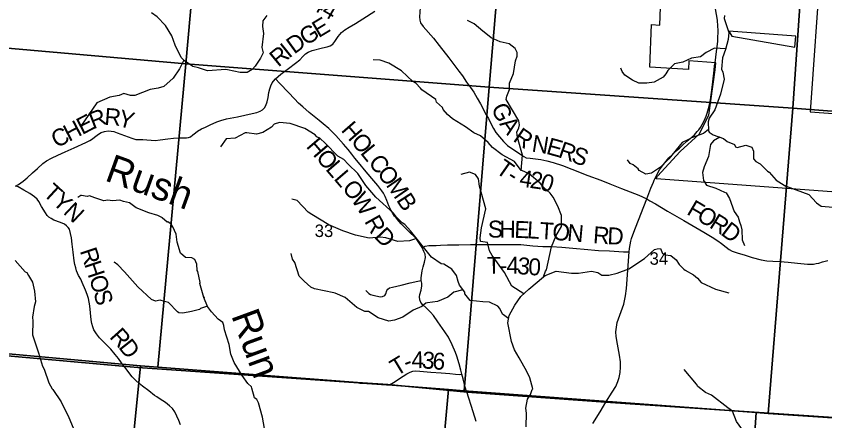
# Model space of a CAD drawing. Extents: x 1878108 to 2183446, y 146837 to 508383.
# Drawn here: x 1990420 to 2004746, y 311060 to 318226 of the extents above; entities that cross this region are included whole.
import ezdxf

# ---------------------------------------------------------------- set-up
doc = ezdxf.new("R2010")
doc.units = 0
for name, color, linetype in [('GM_X_Corporation', 7, 'Continuous'), ('GM_X_County_Road', 7, 'Continuous'), ('GM_X_County_Road_Text', 7, 'Continuous'), ('GM_X_Minor_River', 7, 'Continuous'), ('GM_X_Minor_River_Text', 7, 'Continuous'), ('GM_X_Section', 7, 'Continuous'), ('GM_X_Section_Text', 7, 'Continuous'), ('GM_X_State_Route', 7, 'Continuous'), ('GM_X_Township', 7, 'Continuous'), ('GM_X_Township_Road', 7, 'Continuous'), ('GM_X_Township_Road_Text', 7, 'Continuous')]:
    doc.layers.add(name, color=color, linetype=linetype)

msp = doc.modelspace()

# ---------------------------------------------------------------- linework, layer by layer
at = {"layer": 'GM_X_Corporation'}
for points in [[(2004966, 319101), (2004667, 319124), (2004486, 316532), (2005454, 316459)], [(2005346, 315077), (2001759, 315347), (2001779, 315392), (2002183, 315827), (2002522, 316138), (2002692, 316472), (2002803, 317276), (2002817, 317402), (2002339, 317438), (2002332, 317279), (2001643, 317326), (2001677, 318080), (2001825, 318068), (2001846, 318707)]]:
    msp.add_lwpolyline(points, dxfattribs=at)
msp.add_lwpolyline([(2003046, 317961), (2003096, 317874), (2004216, 317675), (2004230, 317875)], close=True, dxfattribs=at)
at = {"layer": 'GM_X_County_Road'}
for points in [[(1990411, 315215), (1990463, 315243), (1990546, 315306), (1990617, 315365), (1990711, 315450), (1990799, 315530), (1990895, 315617), (1990957, 315663), (1991044, 315711), (1991156, 315762), (1991289, 315821), (1991450, 315892), (1991653, 315988), (1991725, 316022), (1991772, 316051), (1991808, 316082), (1991877, 316137), (1991929, 316164), (1991988, 316183), (1992051, 316193), (1992102, 316192), (1992151, 316182), (1992212, 316161), (1992340, 316113), (1992470, 316067), (1992542, 316045), (1992591, 316042), (1992665, 316043), (1992733, 316038), (1992809, 316028), (1992880, 316027), (1992973, 316039), (1993110, 316056), (1993205, 316068), (1993315, 316070), (1993436, 316071), (1993471, 316076), (1993506, 316091), (1993550, 316123), (1993597, 316161), (1993633, 316191), (1993701, 316229), (1993777, 316261), (1993859, 316301), (1993974, 316353), (1994047, 316381), (1994146, 316406), (1994341, 316445), (1994473, 316471), (1994603, 316501), (1994686, 316520), (1994740, 316542), (1994784, 316567), (1994817, 316600), (1994844, 316643), (1994868, 316708), (1994882, 316784), (1994898, 316876), (1994912, 316939), (1994930, 316991), (1994956, 317045), (1994979, 317078), (1995013, 317115), (1995109, 317198), (1995244, 317299), (1995371, 317393), (1995444, 317452), (1995501, 317512), (1995546, 317558), (1995591, 317589), (1995662, 317616), (1995845, 317666), (1995929, 317681), (1995985, 317702), (1996028, 317733), (1996065, 317779), (1996126, 317869), (1996184, 317937), (1996240, 317982), (1996321, 318032), (1996429, 318099), (1996560, 318179), (1996776, 318316)], [(1992284, 312089), (1992233, 312161), (1992175, 312232), (1992095, 312330), (1992029, 312399), (1991949, 312478), (1991898, 312532), (1991843, 312603), (1991798, 312669), (1991776, 312724), (1991761, 312781), (1991750, 312847), (1991738, 312970), (1991725, 313099), (1991715, 313164), (1991702, 313224), (1991680, 313295), (1991650, 313374), (1991592, 313510), (1991563, 313567), (1991527, 313636), (1991491, 313716), (1991476, 313767), (1991461, 313831), (1991450, 313894), (1991431, 314045), (1991414, 314189), (1991399, 314301), (1991384, 314380), (1991364, 314452), (1991341, 314486), (1991313, 314515), (1991277, 314543), (1991207, 314573), (1991090, 314615), (1991038, 314640), (1990998, 314669), (1990968, 314699), (1990939, 314741), (1990870, 314853), (1990824, 314942), (1990790, 314984), (1990746, 315029), (1990665, 315088), (1990555, 315147), (1990454, 315203), (1990411, 315215)], [(1993331, 310991), (1993301, 311066), (1993269, 311142), (1993229, 311221), (1993187, 311279), (1993139, 311326), (1993063, 311383), (1992972, 311444), (1992913, 311482), (1992872, 311511), (1992770, 311592), (1992660, 311675), (1992600, 311723), (1992548, 311766), (1992477, 311837), (1992398, 311940), (1992332, 312025), (1992300, 312067), (1992284, 312089)]]:
    msp.add_lwpolyline(points, dxfattribs=at)
at = {"layer": 'GM_X_Minor_River'}
for points in [[(1994863, 318240), (1994788, 318144), (1994787, 318042), (1994801, 317920), (1994770, 317669), (1994794, 317579), (1994749, 317481), (1994653, 317341), (1994603, 317284), (1994515, 317228), (1994388, 317230), (1994163, 317278), (1994137, 317280), (1993812, 317259), (1993651, 317309), (1993550, 317336), (1993402, 317436), (1993346, 317492), (1993238, 317713), (1993179, 317878), (1993065, 318062), (1992917, 318215), (1992815, 318285)], [(2002968, 318236), (2002961, 318184), (2003043, 317940), (2003036, 317811), (2002988, 317636), (2002931, 317489), (2002918, 317288), (2002942, 317236), (2002960, 317113), (2002897, 316845), (2002796, 316569), (2002696, 316419), (2002681, 316357), (2002683, 316200), (2002699, 316171), (2002768, 316124), (2002952, 316059), (2003013, 316009), (2003148, 315955), (2003163, 315910), (2003194, 315898), (2003348, 315940), (2003452, 315906), (2003481, 315834), (2003480, 315701), (2003523, 315654), (2003602, 315611), (2003627, 315587), (2003728, 315481), (2003761, 315465), (2003886, 315322), (2004075, 315204)], [(1999368, 315495), (1999391, 315767), (1999301, 316077), (1999292, 316174), (1999323, 316246), (1999339, 316303), (1999328, 316371), (1999102, 316752), (1999115, 316811), (1999159, 316929), (1999160, 317038), (1999232, 317210), (1999264, 317437), (1999296, 317519), (1999294, 317584), (1999261, 317656), (1999154, 317736), (1998993, 317769), (1998834, 317844), (1998714, 317943), (1998685, 317963), (1998531, 318090), (1998415, 318148)], [(2002990, 317645), (2002793, 317661), (2002645, 317585), (2002541, 317509), (2002385, 317484), (2002229, 317410), (2002080, 317380), (2001966, 317267), (2001928, 317205), (2001881, 317144), (2001721, 317060), (2001591, 317037), (2001453, 317042), (2001341, 317090), (2001205, 317182), (2001155, 317246), (2001135, 317305)], [(1993390, 317448), (1993316, 317293), (1993204, 317126), (1993034, 316981), (1992935, 316953), (1992797, 316928), (1992525, 316824), (1992444, 316824), (1992389, 316841), (1992328, 316854), (1992243, 316821), (1992079, 316794), (1991847, 316691), (1991565, 316276)], [(1999379, 315491), (1999368, 315495), (1999248, 315650), (1999030, 315773), (1998856, 315902), (1998781, 315990), (1998648, 316105), (1998530, 316158), (1998380, 316266), (1998149, 316409), (1998062, 316485), (1997984, 316575), (1997972, 316610), (1997866, 316704), (1997853, 316749), (1997606, 316924), (1997585, 316952), (1997503, 317042), (1997449, 317072), (1997249, 317260), (1997023, 317392), (1996866, 317447), (1996746, 317453)], [(1999141, 312874), (1999037, 312951), (1998988, 313047), (1998954, 313088), (1998803, 313160), (1998687, 313170), (1998461, 313192), (1998369, 313307), (1998367, 313339), (1998277, 313464), (1998253, 313530), (1998220, 313634), (1998141, 313744), (1997997, 313835), (1997949, 313840), (1997779, 313960), (1997757, 313990), (1997405, 314426), (1997306, 314537), (1997260, 314569), (1997156, 314664), (1997104, 314736), (1996789, 315023), (1996616, 315228), (1996471, 315437), (1996300, 315608), (1996225, 315687), (1996121, 315746), (1995892, 315979), (1995803, 316060), (1995749, 316088), (1995717, 316122), (1995536, 316237), (1995275, 316323), (1995087, 316344), (1994993, 316314), (1994945, 316263), (1994790, 316167), (1994677, 316139), (1994506, 316158), (1994480, 316158), (1994299, 316066), (1994139, 316052), (1994043, 315910)], [(2002684, 316217), (2002595, 316146), (2002383, 316074), (2002322, 316038), (2002218, 315987), (2001985, 315699), (2001835, 315554), (2001673, 315448), (2001575, 315431), (2001457, 315493), (2001439, 315525), (2001349, 315593), (2001299, 315619), (2001249, 315681)], [(2002887, 316082), (2002771, 316019), (2002722, 315954), (2002685, 315739), (2002609, 315558), (2002580, 315459), (2002598, 315313), (2002651, 315233), (2002818, 315179), (2002971, 315107), (2002999, 315097), (2003057, 315000), (2003139, 314765), (2003209, 314668), (2003237, 314586), (2003257, 314520), (2003277, 314442), (2003283, 314263), (2003321, 314164)], [(1999411, 313307), (1999200, 313445), (1999072, 313689), (1998851, 313990), (1998807, 314069), (1998768, 314215), (1998645, 314237), (1998640, 314302), (1998662, 314477), (1998743, 314814), (1998626, 315216), (1998611, 315345), (1998558, 315422), (1998450, 315461), (1998295, 315425)], [(1999453, 310956), (1999462, 311198), (1999448, 311286), (1999479, 311446), (1999533, 311524), (1999563, 311612), (1999571, 311624), (1999522, 311820), (1999466, 311936), (1999333, 312178), (1999247, 312316), (1999194, 312466), (1999129, 312795), (1999153, 312923), (1999255, 313108), (1999360, 313260), (1999500, 313390), (1999760, 313610), (1999799, 313713), (1999815, 313733), (1999904, 314141), (1999986, 314343), (2000079, 314503), (2000083, 314699), (2000014, 314863), (1999934, 315021), (1999880, 315093), (1999769, 315191), (1999703, 315271), (1999510, 315433), (1999379, 315491)], [(2004062, 315213), (2004460, 315070), (2004598, 314918), (2004680, 314863), (2004896, 314842), (2005164, 314768), (2005755, 314557), (2005985, 314465), (2006145, 314441), (2006267, 314516), (2006291, 314546), (2006337, 314608), (2006397, 314757), (2006397, 314781)], [(1994821, 310923), (1994785, 311123), (1994712, 311377), (1994686, 311437), (1994642, 311469), (1994597, 311641), (1994591, 311661), (1994525, 311719), (1994422, 311863), (1994280, 312091), (1994225, 312241), (1994195, 312411), (1994112, 312670), (1994102, 312746), (1994081, 312800), (1994001, 312860), (1993883, 312988), (1993812, 313084), (1993746, 313242), (1993758, 313248), (1993746, 313244), (1993677, 313492), (1993679, 313508), (1993639, 313706), (1993625, 313720), (1993618, 313834), (1993586, 313918), (1993534, 313946), (1993418, 313955), (1993331, 314031), (1993275, 314221), (1993254, 314363), (1993194, 314497), (1993166, 314541), (1993108, 314583), (1993094, 314577), (1993009, 314655), (1992999, 314659), (1992931, 314697), (1992771, 314746), (1992547, 314832), (1992426, 314920), (1992324, 314942), (1992256, 314967), (1992128, 314955), (1992046, 314967), (1991976, 314957), (1991812, 315009), (1991717, 315042), (1991681, 315032), (1991575, 315048), (1991563, 315050), (1991515, 315012)], [(1997515, 314289), (1997391, 314250), (1997181, 314238), (1996968, 314299), (1996866, 314310), (1996676, 314293), (1996429, 314348), (1996208, 314427), (1995959, 314529), (1995657, 314716), (1995591, 314757), (1995398, 314959), (1995302, 314988)], [(1998336, 313378), (1998174, 313338), (1998065, 313247), (1997885, 313171), (1997709, 313150), (1997679, 313144), (1997606, 313087), (1997453, 313019), (1997268, 312895), (1997120, 312845), (1997022, 312825), (1996833, 312882), (1996662, 312996), (1996600, 312995), (1996454, 313067), (1996247, 313242), (1996071, 313318), (1996046, 313324), (1995707, 313395), (1995641, 313428), (1995520, 313535), (1995433, 313623), (1995355, 313862), (1995313, 313925), (1995294, 314025)], [(1999762, 313611), (1999793, 313634), (1999989, 313713), (2000258, 313675), (2000384, 313674), (2000610, 313713), (2000723, 313687), (2000794, 313642), (2000919, 313640), (2001068, 313676), (2001276, 313752), (2001551, 313934), (2001729, 314095), (2001774, 314108), (2001837, 314114), (2001873, 314025), (2001918, 314002), (2002017, 313987), (2002112, 313908), (2002165, 313828), (2002246, 313748), (2002272, 313728), (2002420, 313646), (2002492, 313587), (2002553, 313510), (2002812, 313390), (2003044, 313326)], [(1990404, 313900), (1990582, 313696), (1990608, 313684), (1990636, 313634), (1990659, 313602), (1990707, 313518), (1990745, 313354), (1990762, 313170), (1990742, 313082), (1990709, 312894), (1990715, 312822), (1990711, 312582), (1990816, 312264), (1990885, 312028), (1990917, 311972), (1991002, 311731), (1991060, 311625), (1991070, 311615), (1991219, 311397), (1991356, 311119), (1991457, 310865)], [(1993811, 313088), (1993688, 313050), (1993670, 313032), (1993526, 312997), (1993374, 312965), (1993300, 312971), (1993278, 312989), (1993118, 313155), (1993048, 313175), (1992971, 313196), (1992891, 313178), (1992817, 313206), (1992578, 313430), (1992340, 313699), (1992223, 313823), (1992159, 313869), (1992159, 313865)], [(2004127, 309586), (2004037, 309660), (2003936, 310065), (2003848, 310216), (2003709, 310380), (2003648, 310545), (2003573, 310663), (2003403, 310809), (2003307, 310874), (2003180, 311048), (2003110, 311232), (2003026, 311290), (2002736, 311515), (2002632, 311560), (2002497, 311668), (2002470, 311706), (2002253, 311968)]]:
    msp.add_lwpolyline(points, dxfattribs=at)
at = {"layer": 'GM_X_Section'}
for points in [[(1988594, 323225), (1993909, 322781), (1993424, 317385), (1988119, 317849)], [(1993909, 322781), (1999255, 322337), (1998801, 316967), (1993424, 317385)], [(1999255, 322337), (2004547, 321948), (2004181, 316598), (1998801, 316967)], [(2004547, 321948), (2009823, 321447), (2009499, 316192), (2004181, 316598)], [(1993424, 317385), (1992928, 312010), (1992620, 312034), (1987478, 312502), (1988119, 317849)], [(1998801, 316967), (1998355, 311588), (1998077, 311612), (1992928, 312010), (1993424, 317385)], [(1998801, 316967), (2004181, 316598), (2003743, 311188), (2003529, 311206), (1998355, 311588)], [(2004181, 316598), (2009499, 316192), (2009160, 310834), (2009010, 310838), (2003743, 311188)], [(1987478, 312502), (1992620, 312034), (1992094, 306704), (1986650, 307162), (1987122, 312538)], [(1992928, 312010), (1998077, 311612), (1997595, 306264), (1992094, 306704), (1992620, 312034)], [(1998077, 311612), (1998355, 311588), (2003529, 311206), (2003175, 305842), (1997595, 306264)], [(2003529, 311206), (2003743, 311188), (2009010, 310838), (2008621, 305452), (2003175, 305842)]]:
    msp.add_lwpolyline(points, close=True, dxfattribs=at)
at = {"layer": 'GM_X_State_Route'}
for points in [[(2002853, 317874), (2002855, 317920), (2002855, 317981), (2002852, 318052), (2002843, 318158), (2002825, 318257), (2002792, 318458), (2002782, 318528), (2002775, 318595), (2002770, 318658), (2002764, 318732), (2002764, 318845), (2002764, 318922)], [(2002794, 317351), (2002801, 317400), (2002829, 317599), (2002849, 317780), (2002852, 317840), (2002853, 317874)], [(2001711, 315287), (2001724, 315319), (2001768, 315414), (2001820, 315502), (2001887, 315597), (2001934, 315656), (2001984, 315715), (2002047, 315777), (2002114, 315841), (2002171, 315888), (2002224, 315941), (2002303, 316011), (2002391, 316084), (2002435, 316126), (2002483, 316183), (2002514, 316216), (2002542, 316256), (2002574, 316308), (2002610, 316374), (2002644, 316457), (2002662, 316511), (2002696, 316631), (2002723, 316747), (2002735, 316836), (2002751, 316961), (2002784, 317268), (2002794, 317351)], [(2000638, 311013), (2000768, 311221), (2000868, 311389), (2000979, 311569), (2001041, 311670), (2001080, 311754), (2001102, 311825), (2001121, 311917), (2001128, 312012), (2001124, 312102), (2001108, 312224), (2001072, 312418), (2001049, 312553), (2001044, 312634), (2001054, 312717), (2001070, 312801), (2001091, 312867), (2001162, 313060), (2001184, 313125), (2001214, 313276), (2001232, 313403), (2001257, 313727), (2001281, 314050), (2001288, 314109), (2001297, 314177), (2001308, 314241), (2001323, 314291), (2001343, 314351), (2001390, 314480), (2001593, 314993), (2001666, 315179), (2001711, 315287)]]:
    msp.add_lwpolyline(points, dxfattribs=at)
at = {"layer": 'GM_X_Township'}
for points in [[(2005605, 311070), (2000862, 311389), (1998407, 311570), (1997006, 311701), (1996554, 311735), (1996485, 311731), (1992576, 312003), (1992305, 312028), (1987495, 312460), (1987075, 312498), (1985839, 312609), (1981647, 312985), (1981968, 316494), (1982170, 318699), (1982896, 327174), (1982963, 327965), (1983031, 328758), (1983804, 337792)], [(1981414, 310431), (1981491, 311280), (1981647, 312985), (1985839, 312609), (1987075, 312498), (1987495, 312460), (1992305, 312028), (1992576, 312003), (1996485, 311731), (1996554, 311735), (1997006, 311701), (1998407, 311570), (2000862, 311389), (2005605, 311070), (2007099, 310961)]]:
    msp.add_lwpolyline(points, dxfattribs=at)
at = {"layer": 'GM_X_Township_Road'}
for points in [[(1997579, 318379), (1997565, 318212), (1997569, 318154), (1997583, 318107), (1997630, 318041), (1997812, 317835), (1997916, 317706), (1998087, 317489), (1998194, 317347), (1998265, 317253), (1998326, 317167), (1998401, 317058), (1998469, 316963), (1998527, 316878), (1998589, 316776), (1998648, 316671), (1998749, 316481), (1998786, 316412), (1998829, 316325), (1998874, 316237), (1998918, 316167), (1998982, 316087), (1999056, 316005), (1999126, 315937), (1999343, 315789), (1999414, 315739), (1999453, 315720), (1999527, 315709), (1999716, 315686), (1999823, 315665), (1999932, 315634), (2000101, 315579), (2000267, 315514), (2000549, 315407), (2000777, 315322), (2000940, 315254), (2001142, 315172), (2001452, 315054), (2001593, 314993), (2001609, 314977), (2001645, 314955), (2001745, 314901), (2001958, 314775), (2002246, 314608), (2002460, 314484), (2002604, 314402), (2002753, 314313), (2002850, 314250), (2002914, 314203), (2002997, 314138), (2003052, 314094), (2003102, 314066), (2003192, 314037), (2003336, 313992), (2003460, 313950), (2003619, 313908), (2003716, 313892), (2003826, 313886), (2003955, 313880), (2004099, 313868), (2004263, 313852), (2004440, 313837), (2004507, 313833), (2004546, 313835), (2004595, 313844), (2004641, 313854), (2004702, 313873), (2004800, 313901)], [(1998401, 311579), (1998376, 311656), (1998342, 311803), (1998318, 311886), (1998300, 311959), (1998268, 312070), (1998228, 312202), (1998202, 312270), (1998146, 312404), (1998079, 312539), (1998012, 312634), (1997889, 312812), (1997813, 312927), (1997763, 312985), (1997682, 313058), (1997624, 313114), (1997592, 313154), (1997571, 313202), (1997566, 313254), (1997573, 313298), (1997596, 313376), (1997609, 313449), (1997606, 313495), (1997595, 313542), (1997595, 313590), (1997601, 313636), (1997614, 313715), (1997631, 313784), (1997653, 313870), (1997670, 313951), (1997667, 314014), (1997643, 314059), (1997612, 314128), (1997565, 314199), (1997518, 314270), (1997471, 314325), (1997408, 314385), (1997326, 314464), (1997243, 314546), (1997167, 314630), (1997124, 314686), (1997094, 314729), (1997066, 314783), (1997025, 314870), (1996985, 314960), (1996956, 315030), (1996926, 315090), (1996900, 315131), (1996825, 315225), (1996723, 315351), (1996594, 315505), (1996514, 315602), (1996421, 315712), (1996364, 315781), (1996299, 315863), (1996220, 315961), (1996085, 316111), (1996015, 316185), (1995959, 316235), (1995861, 316319), (1995787, 316380), (1995612, 316521), (1995498, 316621), (1995424, 316685), (1995350, 316760), (1995246, 316876), (1995093, 317031), (1995013, 317115)], [(1997612, 314128), (1997667, 314152), (1997730, 314164), (1997811, 314162), (1997861, 314164), (1997936, 314173), (1998062, 314177), (1998263, 314176), (1998471, 314184), (1998662, 314183), (1998853, 314182), (1999104, 314185), (1999285, 314185), (1999361, 314183), (1999465, 314169), (1999574, 314157), (1999751, 314149), (1999904, 314146), (2000086, 314137), (2000345, 314111), (2000480, 314100), (2000738, 314079), (2000934, 314068), (2001177, 314055), (2001281, 314050)], [(1996614, 313366), (1996667, 313315), (1996696, 313299), (1996737, 313287), (1996876, 313256), (1996912, 313259), (1996949, 313281), (1996971, 313310), (1996988, 313366), (1997002, 313391), (1997034, 313414), (1997085, 313427), (1997239, 313463), (1997401, 313503), (1997535, 313531), (1997595, 313542)], [(1996979, 311696), (1996994, 311695), (1997021, 311700), (1997041, 311703), (1997077, 311721), (1997132, 311756), (1997213, 311811), (1997344, 311890), (1997401, 311923), (1997448, 311940), (1997501, 311946), (1997570, 311941), (1997768, 311921), (1997950, 311912), (1998105, 311899), (1998206, 311886), (1998271, 311881), (1998318, 311886)], [(1996511, 311728), (1996635, 311721), (1996979, 311696)], [(1998568, 311045), (1998546, 311123), (1998478, 311333), (1998438, 311460), (1998403, 311571), (1998401, 311579)]]:
    msp.add_lwpolyline(points, dxfattribs=at)

# ---------------------------------------------------------------- texts
at = {"layer": 'GM_X_County_Road_Text'}
for s, rotation, p in [('E', 30.9314, (1995779, 317835)), ('G', 31.6922, (1995555, 317697)), ('D', 35.9194, (1995346, 317545)), ('I', 38.9585, (1995253, 317470)), ('R', 39.5534, (1995064, 317314)), ('R', 355.5148, (1991977, 316304)), ('E', 27.3969, (1991590, 316120)), ('R', 21.2136, (1991782, 316220)), ('Y', 345.2521, (1992208, 316287)), ('H', 27.5141, (1991356, 315998)), ('C', 27.519, (1991138, 315884)), ('T', 317.4265, (1990881, 315070)), ('Y', 317.4259, (1991046, 314918)), ('N', 316.8253, (1991240, 314740)), ('R', 288.3294, (1991546, 314070)), ('H', 288.3278, (1991624, 313836)), ('O', 288.2403, (1991707, 313586)), ('S', 284.3635, (1991788, 313340)), ('R', 311.9379, (1992061, 312539)), ('D', 308.1785, (1992222, 312360))]:
    msp.add_text(s, height=300, rotation=rotation, dxfattribs=at).set_placement(p)
at = {"layer": 'GM_X_Minor_River_Text'}
for s, rotation, p in [('Rush', 340.1022, (1991972, 315322)), ('Run', 290.103, (1994226, 312926))]:
    msp.add_text(s, height=500, rotation=rotation, dxfattribs=at).set_placement(p)
at = {"layer": 'GM_X_Section_Text'}
for s, p in [('33', (1995709, 314315)), ('34', (2001642, 313824))]:
    msp.add_text(s, height=221, rotation=0, dxfattribs=at).set_placement(p)
at = {"layer": 'GM_X_Township_Road_Text'}
for s, rotation, p in [('T-444', 330.2903, (1995096, 318667)), ('G', 296.6416, (1998826, 316598)), ('H', 311.0482, (1996164, 316202)), ('A', 305.7352, (1998972, 316317)), ('R', 325.5292, (1999206, 316024)), ('H', 310.591, (1995545, 315914)), ('O', 309.6074, (1996336, 316004)), ('N', 350.9148, (1999543, 315831)), ('E', 344.5526, (1999795, 315792)), ('L', 309.3194, (1996504, 315801)), ('R', 340.6215, (2000006, 315734)), ('S', 339.5204, (2000238, 315652)), ('O', 310.591, (1995717, 315713)), ('C', 309.3123, (1996646, 315628)), ('L', 310.5949, (1995889, 315513)), ('T', 324.9548, (1998897, 315466)), ('L', 310.5881, (1996035, 315342)), ('O', 308.2747, (1996801, 315438)), ('4', 351.0195, (1999322, 315216)), ('2', 351.8072, (1999509, 315187)), ('M', 304.7038, (1996962, 315235)), ('-', 327.8035, (1999095, 315328)), ('0', 343.4406, (1999681, 315163)), ('O', 310.5691, (1996181, 315172)), ('W', 303.1234, (1996346, 314980)), ('B', 303.0108, (1997146, 314969)), ('F', 329.5956, (2002283, 314729)), ('O', 329.5466, (2002457, 314626)), ('R', 299.3418, (1996581, 314594)), ('S', 0, (1998778, 314305)), ('H', 359.4281, (1998980, 314305)), ('E', 357.8052, (1999241, 314302)), ('L', 356.651, (1999464, 314294)), ('R', 328.0747, (2002683, 314493)), ('D', 313.5206, (1996750, 314314)), ('T', 356.4878, (1999688, 314281)), ('O', 355.7851, (1999911, 314267)), ('N', 354.7581, (2000173, 314248)), ('R', 355.8553, (2000633, 314207)), ('D', 357.517, (2000888, 314189)), ('D', 323.0671, (2002887, 314367)), ('T', 0.4886, (1998762, 313662)), ('4', 0.0312, (1999109, 313665)), ('3', 353.5595, (1999285, 313665)), ('0', 356.8276, (1999487, 313643)), ('-', 0.4527, (1998987, 313664)), ('T', 31.2458, (1997160, 311843)), ('4', 0.9072, (1997426, 311990)), ('3', 354.5939, (1997600, 311993)), ('6', 355.2438, (1997787, 311976)), ('-', 20.4697, (1997338, 311952))]:
    msp.add_text(s, height=300, rotation=rotation, dxfattribs=at).set_placement(p)

doc.saveas('drawing.dxf')
